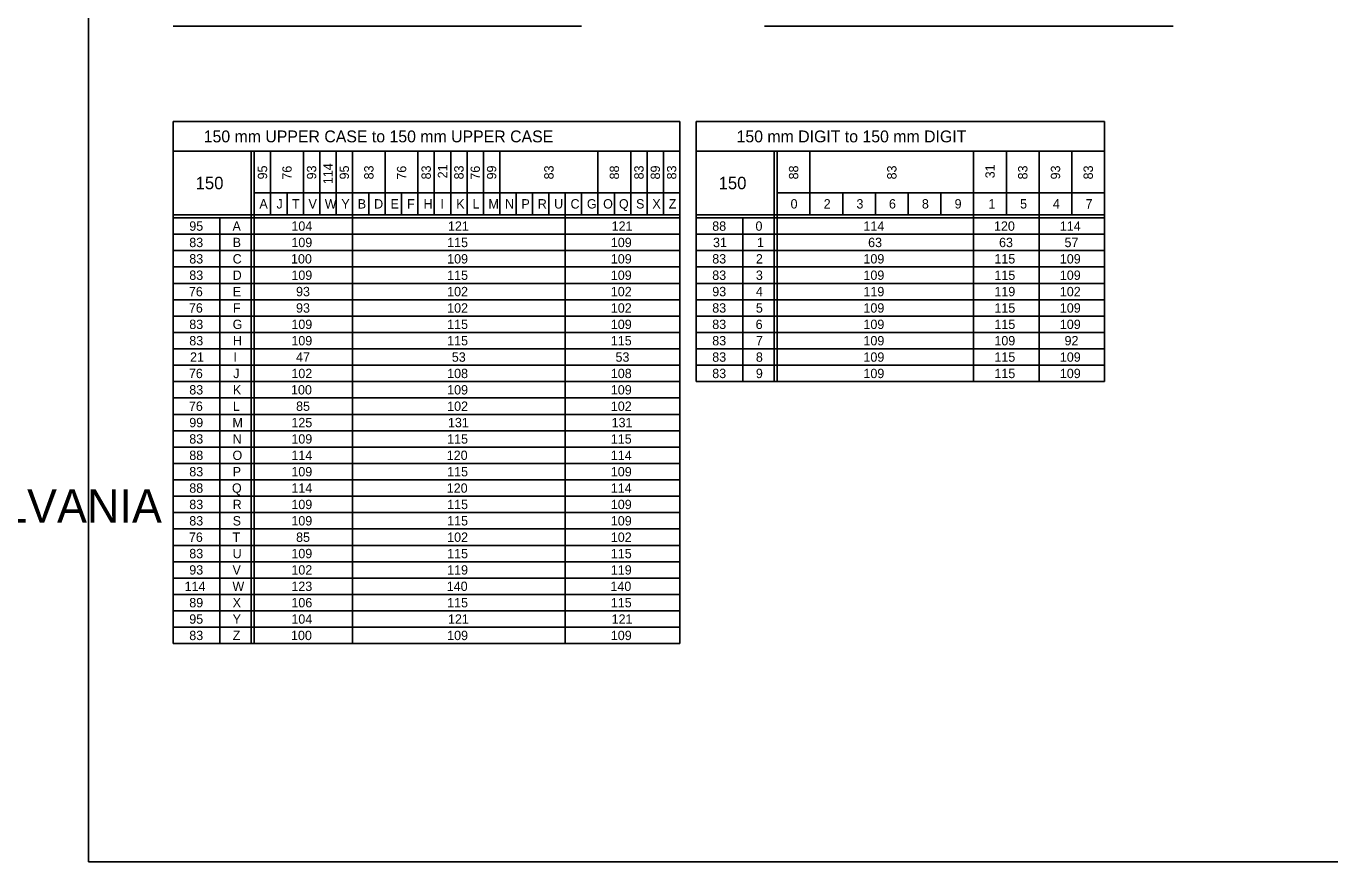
# Model space of a CAD drawing. Extents: x 637580 to 641849, y 297270 to 299646.
# Drawn here: x 638441.3 to 638859.5, y 298472.6 to 298740.6 of the extents above; entities that cross this region are included whole.
import ezdxf

# ---------------------------------------------------------------- set-up
doc = ezdxf.new("R2010")
doc.units = 0
doc.layers.add('1', color=7, linetype='Continuous')
doc.layers.add('2', color=7, linetype='Continuous')

msp = doc.modelspace()

# ---------------------------------------------------------------- linework, layer by layer
at = {"layer": '1'}
for p, q in [((638461.31, 299036.63), (638461.31, 298472.63)), ((639247.31, 298472.63), (638461.31, 298472.63)), ((638461.31, 298472.63), (639047.31, 298472.63))]:
    msp.add_line(p, q, dxfattribs=at)
at = {"layer": '2'}
for p, q in [((638488.51, 298740.63), (638619.51, 298740.63)), ((638678.21, 298740.63), (638809.21, 298740.63)), ((638651.01, 298710), (638488.51, 298710)), ((638488.51, 298710), (638488.51, 298542.63)), ((638651.01, 298710), (638651.01, 298542.63)), ((638787.26, 298710), (638656.26, 298710)), ((638656.26, 298710), (638656.26, 298626.63)), ((638787.26, 298626.63), (638787.26, 298710)), ((638488.51, 298700.5), (638651.01, 298700.5)), ((638513.51, 298700.5), (638513.51, 298542.63)), ((638514.51, 298700.5), (638514.51, 298542.63)), ((638519.76, 298700.5), (638519.76, 298680.13)), ((638530.26, 298700.5), (638530.26, 298680.13)), ((638535.51, 298700.5), (638535.51, 298680.13)), ((638540.76, 298700.5), (638540.76, 298680.13)), ((638546.01, 298700.5), (638546.01, 298542.63)), ((638556.51, 298700.5), (638556.51, 298680.13)), ((638567.01, 298700.5), (638567.01, 298680.13)), ((638572.26, 298700.5), (638572.26, 298680.13)), ((638577.51, 298700.5), (638577.51, 298680.13)), ((638582.76, 298700.5), (638582.76, 298680.13)), ((638588.01, 298700.5), (638588.01, 298680.13)), ((638593.26, 298700.5), (638593.26, 298680.13)), ((638624.76, 298700.5), (638624.76, 298680.13)), ((638635.26, 298700.5), (638635.26, 298680.13)), ((638640.51, 298700.5), (638640.51, 298680.13)), ((638645.76, 298700.5), (638645.76, 298680.13)), ((638656.26, 298700.5), (638787.26, 298700.5)), ((638681.26, 298700.5), (638681.26, 298626.63)), ((638682.26, 298700.5), (638682.26, 298626.63)), ((638692.76, 298700.5), (638692.76, 298680.13)), ((638745.26, 298700.5), (638745.26, 298626.63)), ((638755.76, 298700.5), (638755.76, 298680.13)), ((638766.26, 298700.5), (638766.26, 298626.63)), ((638776.76, 298700.5), (638776.76, 298680.13)), ((638514.51, 298687.13), (638651.01, 298687.13)), ((638525.01, 298687.13), (638525.01, 298680.13)), ((638551.26, 298687.13), (638551.26, 298680.13)), ((638561.76, 298687.13), (638561.76, 298680.13)), ((638598.51, 298687.13), (638598.51, 298680.13)), ((638603.76, 298687.13), (638603.76, 298680.13)), ((638609.01, 298687.13), (638609.01, 298680.13)), ((638609.01, 298687.13), (638609.01, 298680.13)), ((638614.26, 298687.13), (638614.26, 298542.63)), ((638619.51, 298687.13), (638619.51, 298680.13)), ((638630.01, 298687.13), (638630.01, 298680.13)), ((638682.26, 298687.13), (638787.26, 298687.13)), ((638703.26, 298687.13), (638703.26, 298680.13)), ((638713.76, 298687.13), (638713.76, 298680.13)), ((638724.26, 298687.13), (638724.26, 298680.13)), ((638734.76, 298687.13), (638734.76, 298680.13)), ((638651.01, 298680.13), (638488.51, 298680.13)), ((638651.01, 298679.13), (638488.51, 298679.13)), ((638503.51, 298679.13), (638503.51, 298542.63)), ((638787.26, 298680.13), (638656.26, 298680.13)), ((638787.26, 298679.13), (638656.26, 298679.13)), ((638671.26, 298679.13), (638671.26, 298626.63)), ((638651.01, 298673.88), (638488.51, 298673.88)), ((638787.26, 298673.88), (638656.26, 298673.88)), ((638651.01, 298668.63), (638488.51, 298668.63)), ((638787.26, 298668.63), (638656.26, 298668.63)), ((638651.01, 298663.38), (638488.51, 298663.38)), ((638787.26, 298663.38), (638656.26, 298663.38)), ((638651.01, 298658.13), (638488.51, 298658.13)), ((638787.26, 298658.13), (638656.26, 298658.13)), ((638651.01, 298652.88), (638488.51, 298652.88)), ((638787.26, 298652.88), (638656.26, 298652.88)), ((638651.01, 298647.63), (638488.51, 298647.63)), ((638787.26, 298647.63), (638656.26, 298647.63)), ((638651.01, 298642.38), (638488.51, 298642.38)), ((638787.26, 298642.38), (638656.26, 298642.38)), ((638651.01, 298637.13), (638488.51, 298637.13)), ((638787.26, 298637.13), (638656.26, 298637.13)), ((638651.01, 298631.88), (638488.51, 298631.88)), ((638787.26, 298631.88), (638656.26, 298631.88)), ((638651.01, 298626.63), (638488.51, 298626.63)), ((638656.26, 298626.63), (638787.26, 298626.63)), ((638651.01, 298621.38), (638488.51, 298621.38)), ((638651.01, 298616.13), (638488.51, 298616.13)), ((638651.01, 298610.88), (638488.51, 298610.88)), ((638651.01, 298605.63), (638488.51, 298605.63)), ((638651.01, 298600.38), (638488.51, 298600.38)), ((638651.01, 298595.13), (638488.51, 298595.13)), ((638651.01, 298589.88), (638488.51, 298589.88)), ((638651.01, 298584.63), (638488.51, 298584.63)), ((638651.01, 298579.38), (638488.51, 298579.38)), ((638651.01, 298574.13), (638488.51, 298574.13)), ((638651.01, 298568.88), (638488.51, 298568.88)), ((638651.01, 298563.63), (638488.51, 298563.63)), ((638651.01, 298558.38), (638488.51, 298558.38)), ((638651.01, 298553.13), (638488.51, 298553.13)), ((638651.01, 298547.88), (638488.51, 298547.88)), ((638488.51, 298542.63), (638488.51, 298542.63)), ((638488.51, 298542.63), (638651.01, 298542.63))]:
    msp.add_line(p, q, dxfattribs=at)

# ---------------------------------------------------------------- texts
at = {"layer": '1'}
msp.add_text('COMMONWEALTH OF PENNSYLVANIA', height=10.7828, dxfattribs=at).set_placement((638218.9, 298581.36))
at = {"layer": '2'}
for s, height, p in [('150 mm UPPER CASE to 150 mm UPPER CASE', 3.8, (638498.3, 298703.35)), ('150 mm DIGIT to 150 mm DIGIT', 3.8, (638669.21, 298703.35)), ('150', 4, (638495.7, 298688.31)), ('150', 4, (638663.45, 298688.31)), ('A', 3, (638516.16, 298682.13)), ('J', 3, (638521.64, 298682.13)), ('T', 3, (638526.64, 298682.13)), ('V', 3, (638531.91, 298682.13)), ('W', 3, (638537.13, 298682.13)), ('Y', 3, (638542.44, 298682.13)), ('B', 3, (638547.7, 298682.13)), ('D', 3, (638552.95, 298682.13)), ('E', 3, (638558.22, 298682.13)), ('F', 3, (638563.52, 298682.13)), ('H', 3, (638568.79, 298682.13)), ('I', 3, (638574.2, 298682.13)), ('K', 3, (638579.29, 298682.13)), ('L', 3, (638584.54, 298682.13)), ('M', 3, (638589.63, 298682.13)), ('N', 3, (638594.95, 298682.13)), ('P', 3, (638600.2, 298682.13)), ('R', 3, (638605.45, 298682.13)), ('U', 3, (638610.69, 298682.13)), ('C', 3, (638615.95, 298682.13)), ('G', 3, (638621.2, 298682.13)), ('O', 3, (638626.41, 298682.13)), ('Q', 3, (638631.48, 298682.13)), ('S', 3, (638636.97, 298682.13)), ('X', 3, (638642.19, 298682.13)), ('Z', 3, (638647.45, 298682.13)), ('0', 3, (638686.53, 298682.13)), ('2', 3, (638697.16, 298682.13)), ('3', 3, (638707.66, 298682.13)), ('6', 3, (638718.08, 298682.13)), ('8', 3, (638728.66, 298682.13)), ('9', 3, (638739.15, 298682.13)), ('1', 3, (638750, 298682.13)), ('5', 3, (638760.16, 298682.13)), ('4', 3, (638770.66, 298682.13)), ('7', 3, (638781.16, 298682.13)), ('95', 3, (638493.66, 298675)), ('A', 3, (638507.53, 298675)), ('104', 3, (638526.41, 298675)), ('121', 3, (638576.63, 298675)), ('121', 3, (638629.13, 298675)), ('88', 3, (638661.41, 298675)), ('0', 3, (638675.28, 298675)), ('114', 3, (638709.91, 298675)), ('120', 3, (638751.78, 298675)), ('114', 3, (638772.91, 298675)), ('83', 3, (638493.66, 298669.75)), ('B', 3, (638507.58, 298669.75)), ('109', 3, (638526.41, 298669.75)), ('115', 3, (638576.38, 298669.75)), ('109', 3, (638628.88, 298669.75)), ('31', 3, (638661.66, 298669.75)), ('1', 3, (638675.75, 298669.75)), ('63', 3, (638711.41, 298669.75)), ('63', 3, (638753.41, 298669.75)), ('57', 3, (638774.41, 298669.75)), ('83', 3, (638493.66, 298664.5)), ('C', 3, (638507.58, 298664.5)), ('100', 3, (638526.29, 298664.5)), ('109', 3, (638576.38, 298664.5)), ('109', 3, (638628.88, 298664.5)), ('83', 3, (638661.41, 298664.5)), ('2', 3, (638675.41, 298664.5)), ('109', 3, (638709.91, 298664.5)), ('115', 3, (638751.91, 298664.5)), ('109', 3, (638772.91, 298664.5)), ('83', 3, (638493.66, 298659.25)), ('109', 3, (638526.41, 298659.25)), ('109', 3, (638628.88, 298659.25)), ('83', 3, (638661.41, 298659.25)), ('3', 3, (638675.41, 298659.25)), ('109', 3, (638709.91, 298659.25)), ('109', 3, (638772.91, 298659.25)), ('D', 3, (638507.58, 298659.25)), ('115', 3, (638576.38, 298659.25)), ('115', 3, (638751.91, 298659.25)), ('76', 3, (638493.54, 298654)), ('E', 3, (638507.59, 298654)), ('93', 3, (638527.91, 298654)), ('102', 3, (638576.38, 298654)), ('102', 3, (638628.88, 298654)), ('93', 3, (638661.41, 298654)), ('4', 3, (638675.41, 298654)), ('119', 3, (638709.91, 298654)), ('119', 3, (638751.91, 298654)), ('102', 3, (638772.91, 298654)), ('76', 3, (638493.54, 298648.75)), ('F', 3, (638507.65, 298648.75)), ('93', 3, (638527.91, 298648.75)), ('102', 3, (638576.38, 298648.75)), ('102', 3, (638628.88, 298648.75)), ('83', 3, (638661.41, 298648.75)), ('5', 3, (638675.41, 298648.75)), ('109', 3, (638709.91, 298648.75)), ('115', 3, (638751.91, 298648.75)), ('109', 3, (638772.91, 298648.75)), ('83', 3, (638493.66, 298643.5)), ('G', 3, (638507.58, 298643.5)), ('109', 3, (638526.41, 298643.5)), ('115', 3, (638576.38, 298643.5)), ('109', 3, (638628.88, 298643.5)), ('83', 3, (638661.41, 298643.5)), ('6', 3, (638675.33, 298643.5)), ('109', 3, (638709.91, 298643.5)), ('115', 3, (638751.91, 298643.5)), ('109', 3, (638772.91, 298643.5)), ('83', 3, (638493.66, 298638.25)), ('H', 3, (638507.66, 298638.25)), ('109', 3, (638526.41, 298638.25)), ('115', 3, (638576.38, 298638.25)), ('115', 3, (638628.88, 298638.25)), ('83', 3, (638661.41, 298638.25)), ('7', 3, (638675.41, 298638.25)), ('109', 3, (638709.91, 298638.25)), ('109', 3, (638751.91, 298638.25)), ('92', 3, (638774.41, 298638.25)), ('21', 3, (638493.91, 298633)), ('I', 3, (638507.83, 298633)), ('47', 3, (638527.91, 298633)), ('53', 3, (638577.88, 298633)), ('53', 3, (638630.38, 298633)), ('83', 3, (638661.41, 298633)), ('8', 3, (638675.41, 298633)), ('109', 3, (638709.91, 298633)), ('115', 3, (638751.91, 298633)), ('109', 3, (638772.91, 298633)), ('76', 3, (638493.54, 298627.75)), ('J', 3, (638507.77, 298627.75)), ('102', 3, (638526.41, 298627.75)), ('108', 3, (638576.38, 298627.75)), ('108', 3, (638628.88, 298627.75)), ('83', 3, (638661.41, 298627.75)), ('9', 3, (638675.4, 298627.75)), ('109', 3, (638709.91, 298627.75)), ('115', 3, (638751.91, 298627.75)), ('109', 3, (638772.91, 298627.75)), ('83', 3, (638493.66, 298622.5)), ('K', 3, (638507.66, 298622.5)), ('100', 3, (638526.29, 298622.5)), ('109', 3, (638576.38, 298622.5)), ('109', 3, (638628.88, 298622.5)), ('76', 3, (638493.54, 298617.25)), ('L', 3, (638507.66, 298617.25)), ('85', 3, (638527.91, 298617.25)), ('102', 3, (638576.38, 298617.25)), ('102', 3, (638628.88, 298617.25)), ('99', 3, (638493.66, 298612)), ('M', 3, (638507.51, 298612)), ('125', 3, (638526.41, 298612)), ('131', 3, (638576.63, 298612)), ('131', 3, (638629.13, 298612)), ('83', 3, (638493.66, 298606.75)), ('N', 3, (638507.58, 298606.75)), ('109', 3, (638526.41, 298606.75)), ('115', 3, (638576.38, 298606.75)), ('115', 3, (638628.88, 298606.75)), ('88', 3, (638493.66, 298601.5)), ('O', 3, (638507.53, 298601.5)), ('114', 3, (638526.41, 298601.5)), ('120', 3, (638576.25, 298601.5)), ('114', 3, (638628.88, 298601.5)), ('83', 3, (638493.66, 298596.25)), ('P', 3, (638507.58, 298596.25)), ('109', 3, (638526.41, 298596.25)), ('115', 3, (638576.38, 298596.25)), ('109', 3, (638628.88, 298596.25)), ('88', 3, (638493.66, 298591)), ('Q', 3, (638507.35, 298591)), ('114', 3, (638526.41, 298591)), ('120', 3, (638576.25, 298591)), ('114', 3, (638628.88, 298591)), ('83', 3, (638493.66, 298585.75)), ('R', 3, (638507.58, 298585.75)), ('109', 3, (638526.41, 298585.75)), ('115', 3, (638576.38, 298585.75)), ('109', 3, (638628.88, 298585.75)), ('83', 3, (638493.66, 298580.5)), ('S', 3, (638507.59, 298580.5)), ('109', 3, (638526.41, 298580.5)), ('115', 3, (638576.38, 298580.5)), ('109', 3, (638628.88, 298580.5)), ('76', 3, (638493.54, 298575.25)), ('T', 3, (638507.52, 298575.25)), ('85', 3, (638527.91, 298575.25)), ('102', 3, (638576.38, 298575.25)), ('102', 3, (638628.88, 298575.25)), ('83', 3, (638493.66, 298570)), ('U', 3, (638507.57, 298570)), ('109', 3, (638526.41, 298570)), ('115', 3, (638576.38, 298570)), ('115', 3, (638628.88, 298570)), ('93', 3, (638493.66, 298564.75)), ('V', 3, (638507.53, 298564.75)), ('102', 3, (638526.41, 298564.75)), ('119', 3, (638576.38, 298564.75)), ('119', 3, (638628.88, 298564.75)), ('114', 3, (638492.16, 298559.5)), ('W', 3, (638507.51, 298559.5)), ('123', 3, (638526.41, 298559.5)), ('140', 3, (638576.25, 298559.5)), ('140', 3, (638628.75, 298559.5)), ('89', 3, (638493.66, 298554.25)), ('X', 3, (638507.57, 298554.25)), ('106', 3, (638526.41, 298554.25)), ('115', 3, (638576.38, 298554.25)), ('115', 3, (638628.88, 298554.25)), ('95', 3, (638493.66, 298549)), ('Y', 3, (638507.57, 298549)), ('104', 3, (638526.41, 298549)), ('121', 3, (638576.63, 298549)), ('121', 3, (638629.13, 298549)), ('83', 3, (638493.66, 298543.75)), ('Z', 3, (638507.58, 298543.75)), ('100', 3, (638526.29, 298543.75)), ('109', 3, (638576.38, 298543.75)), ('109', 3, (638628.88, 298543.75))]:
    msp.add_text(s, height=height, dxfattribs=at).set_placement(p)
for s, p in [('95', (638518.64, 298691.46)), ('93', (638534.39, 298691.46)), ('114', (638539.64, 298689.96)), ('95', (638544.89, 298691.46)), ('83', (638552.76, 298691.46)), ('83', (638571.14, 298691.46)), ('21', (638576.39, 298691.81)), ('83', (638581.64, 298691.46)), ('99', (638592.14, 298691.45)), ('83', (638610.51, 298691.46)), ('88', (638631.51, 298691.46)), ('83', (638639.39, 298691.46)), ('89', (638644.64, 298691.45)), ('83', (638649.89, 298691.46)), ('88', (638689.01, 298691.46)), ('83', (638720.51, 298691.46)), ('31', (638752.01, 298691.81)), ('83', (638762.51, 298691.46)), ('93', (638773.01, 298691.46)), ('83', (638783.51, 298691.46)), ('76', (638526.51, 298691.38)), ('76', (638563.26, 298691.38)), ('76', (638586.89, 298691.38))]:
    msp.add_text(s, height=3, rotation=90, dxfattribs=at).set_placement(p)

doc.saveas('drawing.dxf')
